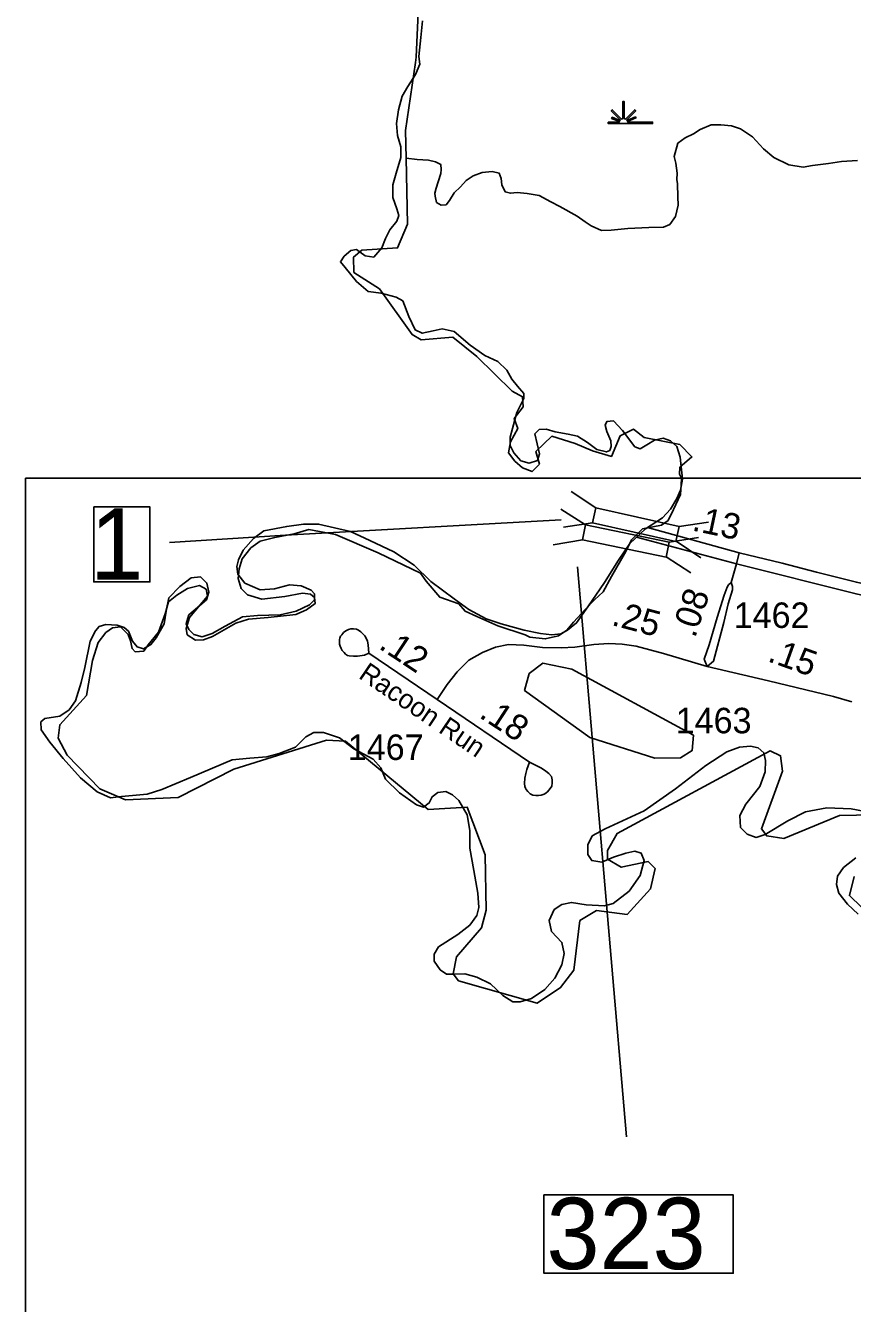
# Model space of a CAD drawing. Extents: x 2532689 to 2764727, y 536648 to 732970.
# Drawn here: x 2549571 to 2553627, y 676552 to 682821 of the extents above; entities that cross this region are included whole.
import ezdxf

# ---------------------------------------------------------------- set-up
doc = ezdxf.new("R2010")
doc.units = 0
for name, color, linetype in [('Exist Boundary Political CountyLine', 7, 'Continuous'), ('Exist Hydrographic Creek Single Shore', 7, 'Continuous'), ('Exist Hydrographic Pond Under 1500 Sq Ft', 7, 'Continuous'), ('Exist Hydrographic Swamp CELL', 7, 'Continuous'), ('Exist Road Primary US Divided Attributed', 7, 'Continuous'), ('Exist Road Primary US Mileage Hundredths English Label', 7, 'Continuous'), ('Exist Road Primary US Structure Standard Bridge CELL', 7, 'Continuous'), ('Exist Road Primary US Structure Standard Bridge Number Label', 7, 'Continuous'), ('Exist Road Secondary Mileage Hundredths English Label', 7, 'Continuous'), ('Exist Road Secondary Structure Standard Bridge Number Label', 7, 'Continuous'), ('Exist Road Secondary Type 51 Attributed', 7, 'Continuous'), ('Exist Road Secondary Type 51 Divided Attributed', 7, 'Continuous'), ('Exist Road Secondary Type 51 Label', 7, 'Continuous'), ('Exist Road Secondary Type 51 Number Label', 7, 'Continuous'), ('Map Preparation Inset Cut Line', 7, 'Continuous')]:
    doc.layers.add(name, color=color, linetype=linetype)

msp = doc.modelspace()

# ---------------------------------------------------------------- linework, layer by layer
at = {"layer": 'Exist Boundary Political CountyLine'}
for points in [[(2551518.5, 682844.8), (2551509.1, 682763.2), (2551499.8, 682670), (2551504.5, 682631.5), (2551483.5, 682580.2), (2551446.2, 682521.9), (2551418.3, 682475.2), (2551399.6, 682407.6), (2551390.3, 682340), (2551395, 682281.7), (2551411.3, 682225.7), (2551411.3, 682174.4), (2551388, 682096.3), (2551371.7, 682040.4), (2551371.7, 681977.4), (2551392.6, 681921.4), (2551402, 681888.8), (2551392.6, 681860.8), (2551357.7, 681818.8), (2551336.7, 681776.9), (2551318.1, 681730.2), (2551278.5, 681684.7), (2551236.5, 681691.7), (2551194.6, 681722.1), (2551166.6, 681717.4), (2551134, 681689.4), (2551115.4, 681661.4), (2551138.7, 681633.4), (2551194.6, 681565.8), (2551250.5, 681516.9), (2551315.7, 681507.5), (2551388, 681488.9), (2551420.6, 681470.2), (2551450.9, 681393.3), (2551481.2, 681328), (2551516.1, 681311.6), (2551569.7, 681323.3), (2551614, 681332.6), (2551672.3, 681321), (2551751.5, 681253.4), (2551823.7, 681202), (2551886.6, 681172.9), (2551930.9, 681130.9), (2551956.5, 681086.6), (2551984.5, 681051.6), (2552014.8, 681016.7), (2552014.8, 680991), (2551979.8, 680923.4), (2551958.9, 680844.1), (2551947.2, 680802.1), (2551947.2, 680760.2), (2551965.9, 680725.2), (2552000.8, 680685.5), (2552040.4, 680673.9), (2552082.4, 680687.9), (2552091.7, 680720.5), (2552080, 680769.5), (2552068.4, 680818.5)], [(2552068.4, 680818.5), (2552089.4, 680839.4), (2552124.3, 680841.8), (2552168.6, 680827.8), (2552231.5, 680816.1), (2552278.1, 680806.8), (2552327, 680776.5), (2552373.6, 680741.5), (2552420.2, 680729.8), (2552436.5, 680736.8), (2552443.5, 680755.5), (2552441.2, 680783.5), (2552422.6, 680830.1), (2552413.2, 680860.4), (2552422.6, 680879.1), (2552455.2, 680881.4), (2552499.5, 680834.8), (2552560, 680754.3), (2552585.7, 680745), (2552618.3, 680763.7), (2552655.6, 680787), (2552697.5, 680796.3), (2552734.8, 680784.6), (2552765.1, 680756.7), (2552781.4, 680703), (2552793.1, 680595.8), (2552783.7, 680542.1), (2552765.1, 680500.2), (2552734.8, 680448.9), (2552695.2, 680406.9), (2552611.3, 680352.1), (2552534.4, 680279.8), (2552478.5, 680198.2), (2552410.9, 680088.6), (2552329.4, 679969.7), (2552273.4, 679890.4), (2552229.2, 679855.4), (2552196.5, 679836.7), (2552152.3, 679832.1), (2552096.3, 679839.1), (2552017.1, 679855.4), (2551902.9, 679885.7), (2551830.7, 679910.2), (2551744.5, 679956.8), (2551672.3, 680008.1), (2551558.1, 680094.4), (2551476.5, 680173.7), (2551376.3, 680239), (2551259.8, 680295), (2551164.3, 680339.3), (2551008.2, 680375.4), (2550933.6, 680375.4), (2550852.1, 680363.7), (2550740.2, 680342.8), (2550688.9, 680305.5), (2550637.7, 680247.2), (2550614.4, 680200.5), (2550607.4, 680167.9), (2550612, 680130.6), (2550647, 680086.3), (2550721.6, 680053.6), (2550791.5, 680058.3), (2550866, 680076.9), (2550922, 680072.3), (2550970.9, 680051.3), (2550987.2, 680032.6), (2550987.2, 680004.6), (2550963.9, 679979), (2550898.7, 679948.7), (2550819.4, 679930), (2550707.6, 679927.7), (2550635.4, 679920.7), (2550549.1, 679874.1), (2550486.2, 679839.1), (2550437.3, 679822.8), (2550395.3, 679834.4), (2550372, 679857.7), (2550358.1, 679885.7), (2550372, 679930), (2550425.6, 679976.7), (2550458.3, 680004.6), (2550469.9, 680042), (2550460.6, 680086.3), (2550428, 680116.6), (2550383.7, 680111.9), (2550327.8, 680069.9), (2550274.2, 680014), (2550262.5, 679958), (2550250.9, 679885.7), (2550211.3, 679816.9), (2550185.6, 679784.3), (2550148.4, 679763.3), (2550118.1, 679772.6), (2550094.8, 679800.6), (2550076.1, 679849.6), (2550055.1, 679868.2), (2550020.2, 679879.9), (2549964.3, 679882.2), (2549931.7, 679872.9), (2549913, 679851.9), (2549887.4, 679800.6)], [(2549887.4, 679800.6), (2549861.7, 679672.4), (2549843.1, 679597.7), (2549815.1, 679509.1), (2549784.9, 679464.8), (2549738.3, 679433.3), (2549666, 679421.7), (2549645, 679405.4), (2549647.4, 679365.7), (2549689.3, 679305.1), (2549754.6, 679225.8), (2549840.8, 679130.2), (2549922.3, 679062.6), (2549987.6, 679032.3), (2550041.2, 679039.3), (2550167, 679050.9), (2550239.2, 679074.2), (2550379, 679132.5), (2550584.1, 679218.8), (2550670.3, 679227), (2550754.2, 679234), (2550814.8, 679250.3), (2550894, 679280.6), (2550945.3, 679331.9), (2550984.9, 679352.9), (2551031.5, 679352.9), (2551110.7, 679327.2), (2551180.6, 679273.6), (2551276.1, 679222.3), (2551313.4, 679180.3), (2551336.7, 679124.4), (2551404.3, 679056.7), (2551488.2, 678998.4), (2551523.1, 678986.8), (2551551.1, 679007.8), (2551565.1, 679038.1), (2551593, 679059.1), (2551632.6, 679063.7), (2551665.3, 679047.4), (2551695.6, 679019.4), (2551737.5, 678949.5), (2551749.2, 678872.5), (2551749.2, 678786.2), (2551770.1, 678676.6), (2551788.8, 678564.7), (2551793.4, 678494.8), (2551784.1, 678455.1), (2551749.2, 678408.5), (2551690.9, 678361.8), (2551595.4, 678301.2), (2551574.4, 678266.2), (2551574.4, 678231.3), (2551604.7, 678189.3), (2551635, 678167.1), (2551676.9, 678167.1), (2551725.9, 678169.5), (2551784.1, 678153.1), (2551851.7, 678120.5), (2551912.3, 678062.2), (2551961.2, 678031.9), (2551996.1, 678031.9), (2552052.1, 678048.2), (2552117.3, 678092.5), (2552166.2, 678148.5), (2552201.2, 678213.8), (2552212.8, 678269.7), (2552201.2, 678323.4), (2552149.9, 678377), (2552138.3, 678430.6), (2552163.9, 678484.3), (2552201.2, 678509.9), (2552247.8, 678519.2), (2552320, 678507.6), (2552410.9, 678502.9), (2552452.9, 678514.6), (2552532.1, 678575.2), (2552585.7, 678652.2), (2552604.3, 678724.5), (2552590.3, 678761.8), (2552560, 678771.1), (2552515.8, 678761.8), (2552455.2, 678740.8), (2552396.9, 678717.5), (2552348, 678724.5), (2552329.4, 678754.8), (2552329.4, 678801.4), (2552350.3, 678845.7), (2552413.2, 678880.7), (2552604.3, 678969.3), (2552758.1, 679076.6), (2552907.2, 679190.8), (2553009.8, 679258.4), (2553072.7, 679281.8), (2553126.3, 679286.4), (2553163.5, 679277.1), (2553191.5, 679253.8), (2553200.8, 679216.5), (2553198.5, 679160.5), (2553172.9, 679088.2), (2553103, 679001.9), (2553075, 678946)], [(2553075, 678946), (2553077.3, 678887.7), (2553110, 678855), (2553154.2, 678838.7), (2553198.5, 678852.7), (2553310.3, 678920.3), (2553396.6, 678964.6), (2553501.4, 678983.3), (2553620.3, 678978.6), (2553680.8, 678967)], [(2553643.6, 678738.4), (2553583, 678690.6), (2553552.7, 678648.7), (2553548, 678606.7), (2553559.7, 678564.7), (2553601.6, 678511.1), (2553655.2, 678462.1)]]:
    msp.add_lwpolyline(points, dxfattribs=at)
at = {"layer": 'Exist Hydrographic Creek Single Shore'}
for points in [[(2551482.6, 682640.3), (2551486.2, 682666.1), (2551510.2, 683172.6)], [(2551437, 682170.6), (2551434.4, 682306.1), (2551482.6, 682640.3)], [(2551437, 682170.6), (2551490.8, 682163.8), (2551546.7, 682160.5), (2551581.4, 682152), (2551608, 682139.2), (2551609.1, 682115.2), (2551608, 682095), (2551594.1, 682054.2), (2551585.5, 682023.7), (2551578.5, 681999.4), (2551579.3, 681983.4), (2551586.7, 681953.6), (2551609.3, 681940.6), (2551633.3, 681941.8), (2551650.3, 681962.6), (2551672.6, 681999.8), (2551703.4, 682029.3), (2551731.9, 682060.7), (2551766.6, 682084.5), (2551809.8, 682100.6), (2551859.8, 682104.9), (2551894.1, 682096.5), (2551903.3, 682070.8), (2551906.8, 682038.9), (2551922.6, 682005.5), (2551948.8, 681998.8), (2551982.5, 682002.3), (2552031.1, 681996.6), (2552089.3, 681987.3), (2552146.7, 681955.9), (2552192, 681933.9), (2552276.3, 681885.7), (2552315.9, 681857.5), (2552344.6, 681838.8), (2552395.9, 681815.1), (2552443.6, 681817.3), (2552525.2, 681825.2), (2552627.2, 681830), (2552699.1, 681831.4), (2552730.5, 681844.9), (2552758.6, 681884.4), (2552772.1, 681939.2), (2552770.1, 681981.2), (2552769, 682045.4), (2552766, 682065.3), (2552766.6, 682097.5), (2552760.2, 682145.3), (2552752.6, 682179), (2552769.7, 682244), (2552806.4, 682269.8), (2552847.4, 682289.8), (2552880.4, 682311.4), (2552933.3, 682334), (2552981.3, 682334.2), (2553033.6, 682328.7), (2553078.3, 682314.8), (2553136.3, 682275.3), (2553191, 682215.7), (2553241.1, 682173.9), (2553314.9, 682137.3), (2553385.4, 682126.6), (2553431.2, 682134.7), (2553508.7, 682144.4), (2553572.2, 682153.4), (2553652, 682159.1)], [(2552596.3, 680352.9), (2552689.8, 680370.8), (2552723.1, 680393.5), (2552748.3, 680447.1), (2552784, 680521.1), (2552786.4, 680565.8), (2552788.9, 680600.7), (2552777.5, 680621), (2552779.9, 680654.3), (2552839.4, 680705.1), (2552779.3, 680765.1), (2552604.4, 680800.7), (2552553.3, 680841.3), (2552487.3, 680809.1), (2552444, 680707.6), (2552351.3, 680735.2), (2552266.8, 680770.9), (2552151.5, 680806.7), (2552073.5, 680731.9), (2552091.3, 680668.6), (2552055.6, 680632.8), (2552008.5, 680650.7), (2551971.1, 680684.8), (2551940.2, 680725.4), (2551949.1, 680778.2), (2551984.9, 680844.9), (2551967, 680893.6), (2552010.9, 680950.5), (2552008.3, 680999.8), (2551957.3, 681026.9), (2551785, 681197.5), (2551666.4, 681291.7), (2551510.4, 681278.7), (2551466.5, 681304.7), (2551307.2, 681529.5), (2551180.3, 681609.7), (2551179.3, 681685.2), (2551220.3, 681719.7), (2551395.4, 681730), (2551443.4, 681846.9), (2551437, 682170.6)], [(2549898.8, 679706.9), (2549927.2, 679793.9), (2549963.8, 679843.6), (2549997.1, 679867), (2550036.9, 679871.9), (2550074.3, 679833.7), (2550085.7, 679802.8), (2550093, 679764.6), (2550108.4, 679749.2), (2550150.7, 679751.6), (2550172.3, 679782.9), (2550222.6, 679845.5), (2550255.9, 679935.7), (2550271.3, 679993.4), (2550311.9, 680026.7), (2550365.6, 680060), (2550424.1, 680073.8), (2550456.6, 680055.9), (2550463.1, 680021.8), (2550374.5, 679917), (2550359.1, 679863.4), (2550363.1, 679832.5), (2550403.8, 679805.7), (2550443.6, 679808.1), (2550488.3, 679823.5), (2550602.4, 679888.9), (2550665, 679908.4), (2550760.9, 679917.4), (2550896.5, 679931.2), (2550948.5, 679955.6), (2550990.8, 679985.6), (2550988.4, 680015.7), (2550968, 680032), (2550929.4, 680037.2), (2550841.7, 680021), (2550729.6, 680006.4), (2550658.9, 680028.3), (2550628.8, 680060), (2550614.2, 680108.7), (2550618.3, 680155.9), (2550633.7, 680205.4), (2550675.9, 680259), (2550721.4, 680291.5), (2550792.9, 680309.4), (2550888, 680327.3), (2550959.9, 680349.6), (2551091.5, 680324.5), (2551300, 680234.7), (2551507.5, 680135.1), (2551536, 680095.3), (2551602.6, 680017.3), (2551695.2, 679984), (2551726.9, 679949.1), (2551784.6, 679922.3), (2551887, 679876.8), (2552021.9, 679832.1), (2552043.8, 679821.5), (2552119.8, 679812.2), (2552184.8, 679827.6), (2552225.4, 679854.4), (2552258.7, 679894.2), (2552318, 679958.4), (2552361.1, 680003.1), (2552404.2, 680043.7), (2552444.4, 680118.9), (2552514.3, 680241.6), (2552542.7, 680297.6), (2552596.3, 680352.9)], [(2553729.3, 678948.7), (2553563.4, 678945.2), (2553289.5, 678832.4), (2553206.4, 678845.4), (2553180.4, 678880.5), (2553283.3, 679163.7), (2553274.3, 679238.9), (2553223.4, 679263.1), (2552472.3, 678858.4), (2552424.4, 678774.3), (2552425.4, 678731.7), (2552492.4, 678691.8), (2552625.3, 678720.1), (2552659.3, 678685.4), (2552636.4, 678585.9), (2552521.3, 678459.8), (2552371.5, 678480), (2552289.4, 678430.7), (2552260.3, 678186.6), (2552195.3, 678101.9), (2552079.5, 678025), (2551694.4, 678134.2), (2551668.3, 678169.2), (2551684.3, 678251.9), (2551806.3, 678394.8), (2551829.3, 678481), (2551824.4, 678753.3), (2551737.4, 678986.1), (2551545.3, 678975.1), (2551139.3, 679310), (2551047.4, 679316.1), (2550592.4, 679172.8), (2550319.3, 679033.8), (2550061.3, 679023.3), (2549935.2, 679077.3), (2549774.3, 679241.5), (2549731.4, 679325.1), (2549738.4, 679391.1), (2549869.4, 679534.2), (2549898.8, 679706.9)], [(2553730.3, 678439.8), (2553611.4, 678553.3), (2553635.4, 678646.1)]]:
    msp.add_lwpolyline(points, dxfattribs=at)
at = {"layer": 'Exist Hydrographic Pond Under 1500 Sq Ft'}
msp.add_lwpolyline([(2552657.3, 679227), (2552339.3, 679329), (2552018.4, 679559), (2552041.3, 679642), (2552107.3, 679693.9), (2552249.4, 679663.5), (2552847.4, 679339.7), (2552840.4, 679264), (2552782.4, 679228.8), (2552657.3, 679227)], dxfattribs=at)
at = {"layer": 'Exist Hydrographic Swamp CELL'}
msp.add_lwpolyline([(2552429, 682347.3), (2552481.7, 682347.3), (2552483.7, 682351), (2552445.4, 682365.8), (2552448.3, 682371), (2552486.1, 682355.2), (2552487.7, 682358.1), (2552443.2, 682402.7), (2552448.4, 682407.8), (2552493.6, 682362.3), (2552500, 682364.7), (2552500, 682447.8), (2552507.2, 682447.8), (2552507.2, 682364.7), (2552513.5, 682362.3), (2552558.8, 682407.8), (2552564, 682402.7), (2552519.5, 682358.1), (2552521.5, 682354.5), (2552562.4, 682373.1), (2552564.9, 682368.1), (2552523.9, 682350.3), (2552525.5, 682347.3), (2552646.5, 682347.3), (2552646.5, 682340.2), (2552429, 682340.2)], close=True, dxfattribs=at)
at = {"layer": 'Exist Road Primary US Divided Attributed'}
for points in [[(2553071.4, 680234.5), (2552621.6, 680358.8)], [(2552568.1, 680311.5), (2553057.4, 680181)], [(2554567.7, 679896.5), (2553989.2, 680013.1), (2553646.5, 680090), (2553451.1, 680140.4), (2553282.6, 680183.7), (2553071.4, 680234.5)], [(2553057.4, 680181), (2553644.5, 680032.8), (2553963.6, 679961.9), (2554549.4, 679842.8)]]:
    msp.add_lwpolyline(points, dxfattribs=at)
at = {"layer": 'Exist Road Primary US Structure Standard Bridge CELL'}
for p, q in [((2552247.4, 680535.6), (2552368.3, 680455.1)), ((2552196.6, 680449.2), (2552318, 680371.1)), ((2552209.3, 680360.4), (2552352.3, 680381.6)), ((2552777, 680363), (2552920, 680384.2)), ((2552158.3, 680274), (2552301.9, 680297.6)), ((2552728.2, 680286.4), (2552871.8, 680309.9)), ((2552761.3, 680291.1), (2552882.2, 680210.6)), ((2552712.5, 680214.5), (2552833.8, 680136.4))]:
    msp.add_line(p, q, dxfattribs=at)
for points in [[(2552368.3, 680455.1), (2552777.1, 680363.3), (2552761.1, 680289.8), (2552352.3, 680381.6)], [(2552318, 680371.1), (2552728.3, 680286.7), (2552712.2, 680213.2), (2552301.9, 680297.6)]]:
    msp.add_lwpolyline(points, close=True, dxfattribs=at)
at = {"layer": 'Exist Road Primary US Structure Standard Bridge Number Label'}
for points in [[(2549904.9, 680459.7), (2550180.6, 680459.7), (2550180.6, 680091.5), (2549904.9, 680091.5)], [(2552113.2, 677084.9), (2553042.2, 677084.9), (2553042.2, 676700.8), (2552113.2, 676700.8)]]:
    msp.add_lwpolyline(points, close=True, dxfattribs=at)
at = {"layer": 'Exist Road Secondary Structure Standard Bridge Number Label'}
for points in [[(2552197.2, 680396.6), (2550845.7, 680321.5), (2550276.5, 680285.9)], [(2552277.6, 680165.3), (2552519, 677369.7)]]:
    msp.add_lwpolyline(points, dxfattribs=at)
at = {"layer": 'Exist Road Secondary Type 51 Attributed'}
for points in [[(2553071.4, 680234.5), (2553057.4, 680181)], [(2553057.4, 680181), (2553032.2, 680088.6)], [(2551235, 679827.5), (2551225.1, 679837.9), (2551214.7, 679846.9), (2551203.7, 679855.9), (2551193.3, 679859.9), (2551179.3, 679861.9), (2551166.9, 679861.9), (2551154.4, 679858.4), (2551141.5, 679852.4), (2551131, 679844), (2551126.2, 679838.1)], [(2551126.2, 679838.1), (2551122.1, 679833), (2551116.1, 679825.6), (2551112.6, 679816.6), (2551111.1, 679808.6), (2551110.6, 679795.2), (2551111.1, 679786.7), (2551113.5, 679776.2), (2551118, 679764.8), (2551123.5, 679754.8), (2551132.9, 679745.3), (2551140.4, 679737.4), (2551150.3, 679731.4), (2551158.8, 679728.4), (2551178.7, 679727.4), (2551198.6, 679726.8), (2551233, 679732.8), (2551254.1, 679743)], [(2551254.1, 679743), (2551251.4, 679783.1), (2551247.5, 679801.5), (2551241, 679816), (2551235, 679827.5)], [(2552913.4, 679677.1), (2552699.7, 679741.4), (2552565.5, 679777.3), (2552497.2, 679786.9), (2552432.5, 679789.3), (2552358.2, 679784.5), (2552264.7, 679772.5), (2552197.6, 679767.8), (2552106.6, 679770.2), (2552015.5, 679782.1), (2551938.8, 679784.5), (2551876.5, 679772.5), (2551811.8, 679746.2), (2551744.7, 679707.9), (2551687.2, 679650.4), (2551639.3, 679588.1), (2551588.9, 679515.5)], [(2551254.1, 679743), (2551588.9, 679515.5)], [(2553623.5, 679503.9), (2553533.1, 679529.4), (2553214.4, 679606.1), (2552913.4, 679677.1)], [(2551588.9, 679515.5), (2552042.1, 679208.1)], [(2552023.6, 679080.3), (2552019.3, 679088.8), (2552017.8, 679102.7), (2552019.9, 679128.7), (2552024.9, 679151.6), (2552029.9, 679171.5), (2552042.1, 679208.1)], [(2552042.1, 679208.1), (2552102.1, 679177.4), (2552122.4, 679163.4), (2552136.9, 679151.9), (2552150.3, 679136.5), (2552154.3, 679121.5), (2552154.2, 679106.6), (2552152.2, 679089.7), (2552143.8, 679077.7), (2552130.3, 679061.3), (2552117, 679052)], [(2552117, 679052), (2552113.9, 679049.8), (2552099.4, 679044.9), (2552087.5, 679043.9), (2552074, 679043.9), (2552059.6, 679045.4), (2552046.2, 679052.4), (2552034.2, 679064.4), (2552026.8, 679073.8), (2552023.6, 679080.3)]]:
    msp.add_lwpolyline(points, dxfattribs=at)
at = {"layer": 'Exist Road Secondary Type 51 Divided Attributed'}
for points in [[(2553032.2, 680088.6), (2553018.5, 680077.2), (2553011.5, 680065.9), (2552997.2, 680027), (2552962.7, 679916.8), (2552923.7, 679782.6), (2552898.5, 679712.6), (2552913.4, 679677.1)], [(2553032.2, 680088.6), (2553038.4, 680069.8), (2553038.5, 680053.4), (2553017.8, 679984.5), (2552996, 679892.8), (2552945.5, 679702.3), (2552913.4, 679677.1)]]:
    msp.add_lwpolyline(points, dxfattribs=at)
at = {"layer": 'Map Preparation Inset Cut Line'}
msp.add_lwpolyline([(2549570.7, 680600.4), (2610045.1, 680600.4), (2610045.1, 636351.9), (2549570.7, 636351.9)], close=True, dxfattribs=at)

# ---------------------------------------------------------------- texts
at = {"layer": 'Exist Road Primary US Mileage Hundredths English Label'}
msp.add_text('.13', height=125, rotation=348.07374, dxfattribs=at).set_placement((2552835.4, 680344.7))
at = {"layer": 'Exist Road Primary US Structure Standard Bridge Number Label'}
for s, p in [('1', (2549887.4, 680103.4)), ('323', (2552125.7, 676720.6))]:
    msp.add_text(s, height=350, dxfattribs=at).set_placement(p)
at = {"layer": 'Exist Road Secondary Mileage Hundredths English Label'}
for s, rotation, p in [('.08', 71.57568, (2552854.2, 679812.7)), ('.25', 345.13936, (2552440.4, 679881.1)), ('.12', 326.4759, (2551297.9, 679768.6)), ('.15', 340.3914, (2553205.4, 679703.9)), ('.18', 326.802, (2551790.4, 679430.2))]:
    msp.add_text(s, height=125, rotation=rotation, dxfattribs=at).set_placement(p)
at = {"layer": 'Exist Road Secondary Type 51 Label'}
msp.add_text('Racoon Run', height=95, rotation=325.85003, dxfattribs=at).set_placement((2551199.4, 679623.2))
at = {"layer": 'Exist Road Secondary Type 51 Number Label'}
for s, p in [('1462', (2553044.1, 679866)), ('1463', (2552759.7, 679349.2)), ('1467', (2551151.3, 679218.3))]:
    msp.add_text(s, height=125, dxfattribs=at).set_placement(p)

doc.saveas('drawing.dxf')
